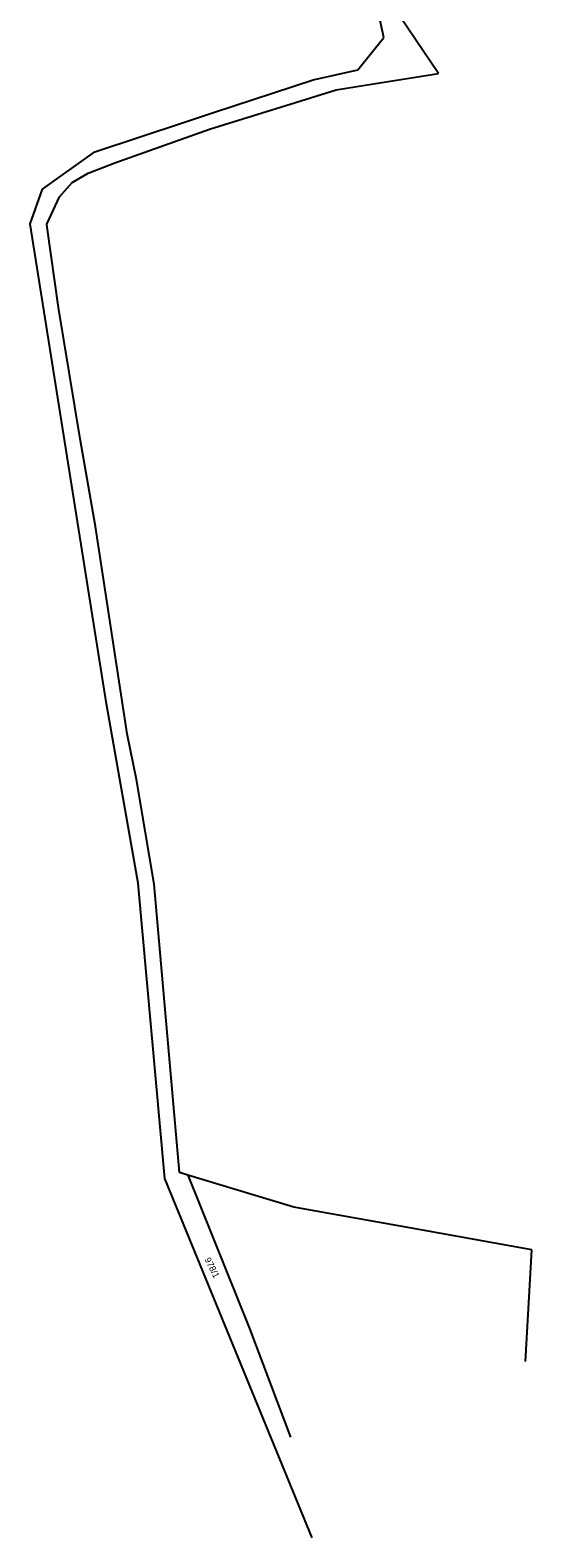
# Model space of a CAD drawing. Extents: x -749173 to -746119, y -1132678 to -1130338.
# Drawn here: x -747337.3 to -747205.5, y -1132678 to -1132282 of the extents above; entities that cross this region are included whole.
import ezdxf

# ---------------------------------------------------------------- set-up
doc = ezdxf.new("R2010")
doc.units = 0
for name, color, linetype in [('Vrstva 1', 7, 'Continuous'), ('Vrstva 13', 7, 'Continuous'), ('Vrstva 18', 7, 'Continuous')]:
    doc.layers.add(name, color=color, linetype=linetype)

msp = doc.modelspace()

# ---------------------------------------------------------------- linework, layer by layer
at = {"layer": 'Vrstva 1'}
for points in [[(-747244.35, -1132283.92), (-747248.16, -1132266.52)], [(-747251.22, -1132292.4), (-747244.35, -1132283.92)], [(-747289.13, -1132303.67), (-747262.97, -1132295.03)], [(-747262.97, -1132295.03), (-747251.22, -1132292.4)], [(-747320.31, -1132313.98), (-747296.72, -1132306.18)], [(-747296.72, -1132306.18), (-747289.13, -1132303.67)], [(-747334.04, -1132323.78), (-747320.31, -1132313.98)], [(-747337.26, -1132332.85), (-747334.04, -1132323.78)], [(-747317.24, -1132458.97), (-747337.26, -1132332.85)], [(-747308.87, -1132506.03), (-747317.24, -1132458.97)], [(-747301.9, -1132583.56), (-747308.87, -1132506.03)], [(-747263.19, -1132677.97), (-747301.9, -1132583.56)], [(-747295.89, -1132582.7), (-747279.64, -1132623.02)], [(-747279.64, -1132623.02), (-747268.86, -1132651.49)]]:
    msp.add_lwpolyline(points, dxfattribs=at)
at = {"layer": 'Vrstva 13'}
for points in [[(-747230, -1132293.43), (-747248.16, -1132266.52)], [(-747249.27, -1132296.46), (-747230, -1132293.43)], [(-747267.6, -1132300.99), (-747256.92, -1132297.67)], [(-747256.92, -1132297.67), (-747249.27, -1132296.46)], [(-747290.17, -1132308.02), (-747267.6, -1132300.99)], [(-747315.01, -1132316.89), (-747290.17, -1132308.02)], [(-747322, -1132319.58), (-747315.01, -1132316.89)], [(-747329.55, -1132325.78), (-747326.26, -1132322.01)], [(-747326.26, -1132322.01), (-747322, -1132319.58)], [(-747332.87, -1132332.92), (-747329.55, -1132325.78)], [(-747332.76, -1132333.73), (-747332.87, -1132332.92)], [(-747329.82, -1132354.84), (-747332.76, -1132333.73)], [(-747324.1, -1132389.32), (-747329.82, -1132354.84)], [(-747320.12, -1132412.33), (-747324.1, -1132389.32)], [(-747311.81, -1132466.78), (-747320.12, -1132412.33)], [(-747309.37, -1132478.82), (-747311.81, -1132466.78)], [(-747304.7, -1132506.26), (-747309.37, -1132478.82)], [(-747298.07, -1132582.05), (-747304.7, -1132506.26)], [(-747295.89, -1132582.7), (-747298.07, -1132582.05)], [(-747279.04, -1132587.77), (-747295.89, -1132582.7)], [(-747267.98, -1132591.09), (-747279.04, -1132587.77)], [(-747258.75, -1132592.75), (-747267.98, -1132591.09)], [(-747238.06, -1132596.46), (-747258.75, -1132592.75)], [(-747220.55, -1132599.6), (-747238.06, -1132596.46)], [(-747205.5, -1132602.3), (-747220.55, -1132599.6)], [(-747207.17, -1132631.63), (-747205.5, -1132602.3)]]:
    msp.add_lwpolyline(points, dxfattribs=at)

# ---------------------------------------------------------------- texts
at = {"layer": 'Vrstva 18'}
msp.add_text('978/1', height=1.7, rotation=296.7496, dxfattribs=at).set_placement((-747291.51, -1132604.84))

doc.saveas('drawing.dxf')
